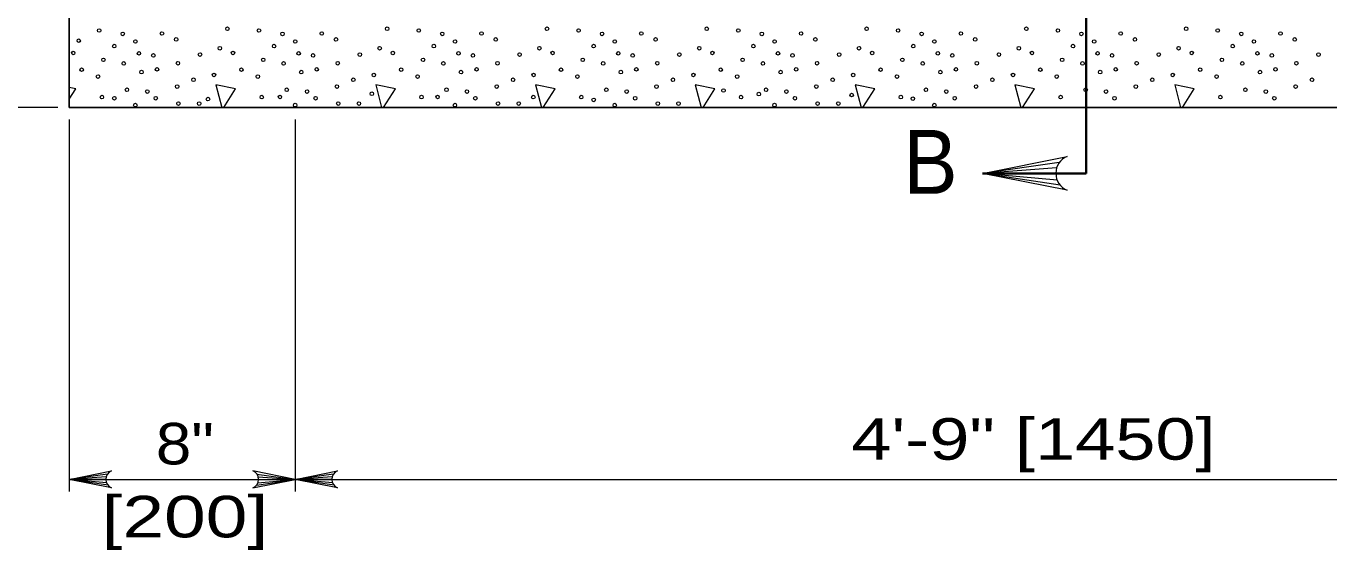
# Model space of a CAD drawing. Extents: x 1352.5 to 1386.5, y 735.9 to 779.9.
# Drawn here: x 1359.407 to 1364.306, y 769.001 to 770.968 of the extents above; entities that cross this region are included whole.
import ezdxf
from ezdxf.enums import TextEntityAlignment as Align

# ---------------------------------------------------------------- set-up
doc = ezdxf.new("R2010")
doc.units = 0
doc.header["$LTSCALE"] = 0.062
doc.layers.add('1', color=7, linetype='Continuous', lineweight=13)

msp = doc.modelspace()

# ---------------------------------------------------------------- linework, layer by layer
at = {"layer": '1', "lineweight": 35}
for p, q in [((1363.393, 771.60092), (1363.393, 770.5645)), ((1363.393, 770.5645), (1363.393, 770.41492)), ((1363.393, 770.41492), (1363.00358, 770.41492))]:
    msp.add_line(p, q, dxfattribs=at)
at = {"layer": '1'}
for p, q in [((1360.12142, 770.747), (1360.14375, 770.66242)), ((1360.19517, 770.73258), (1360.12142, 770.747)), ((1360.15067, 770.66242), (1360.19517, 770.73258)), ((1360.72225, 770.747), (1360.74442, 770.66242)), ((1360.79592, 770.73258), (1360.72225, 770.747)), ((1360.75142, 770.66242), (1360.79592, 770.73258)), ((1361.323, 770.747), (1361.34517, 770.6625)), ((1361.39667, 770.73258), (1361.323, 770.747)), ((1361.35208, 770.6625), (1361.39667, 770.73258)), ((1361.92367, 770.747), (1361.94592, 770.6625)), ((1361.9975, 770.73258), (1361.92367, 770.747)), ((1361.95283, 770.6625), (1361.9975, 770.73258)), ((1362.52442, 770.747), (1362.54667, 770.6625)), ((1362.59825, 770.73258), (1362.52442, 770.747)), ((1362.55358, 770.6625), (1362.59825, 770.73258)), ((1363.12525, 770.747), (1363.1475, 770.6625)), ((1363.726, 770.747), (1363.74825, 770.6625)), ((1363.79975, 770.73258), (1363.726, 770.747)), ((1363.75517, 770.6625), (1363.79975, 770.73258)), ((1359.52733, 770.66242), (1357.68633, 770.66242)), ((1359.56983, 770.61742), (1359.56983, 769.22067)), ((1360.41942, 770.61742), (1360.41942, 769.22067)), ((1363.29208, 770.45525), (1363.00358, 770.41492)), ((1363.28225, 770.43525), (1363.00358, 770.41492)), ((1363.27933, 770.41492), (1363.00358, 770.41492)), ((1363.28442, 770.389), (1363.00358, 770.41492)), ((1363.29542, 770.37025), (1363.00358, 770.41492)), ((1359.714, 769.28583), (1359.56983, 769.26567)), ((1359.70917, 769.27583), (1359.56983, 769.26567)), ((1359.70767, 769.26567), (1359.56983, 769.26567)), ((1359.71025, 769.25275), (1359.56983, 769.26567)), ((1359.71575, 769.24333), (1359.56983, 769.26567)), ((1360.2735, 769.24333), (1360.41942, 769.26567)), ((1360.27517, 769.28583), (1360.41942, 769.26567)), ((1360.279, 769.25275), (1360.41942, 769.26567)), ((1360.28008, 769.27583), (1360.41942, 769.26567)), ((1360.28158, 769.26567), (1360.41942, 769.26567)), ((1360.56367, 769.28583), (1360.41942, 769.26567)), ((1360.55875, 769.27583), (1360.41942, 769.26567)), ((1360.55725, 769.26567), (1360.41942, 769.26567)), ((1360.55983, 769.25275), (1360.41942, 769.26567)), ((1360.56533, 769.24333), (1360.41942, 769.26567))]:
    msp.add_line(p, q, dxfattribs=at)
at = {"layer": '1', "lineweight": 25}
msp.add_lwpolyline([(1358.38042, 774.73258), (1359.56983, 774.73258), (1359.56983, 770.66242), (1367.21625, 770.66242), (1367.21625, 774.73258), (1368.40567, 774.73258), (1369.78625, 774.73258)], dxfattribs=at)
at = {"layer": '1'}
for points in [[(1359.56983, 770.69392), (1359.59442, 770.73258), (1359.56983, 770.7375)], [(1363.15433, 770.6625), (1363.19892, 770.73258), (1363.12525, 770.747)], [(1363.32225, 770.35117), (1363.00358, 770.41492), (1363.32225, 770.47858)], [(1359.72908, 769.23383), (1359.56983, 769.26567), (1359.72908, 769.2975)], [(1359.56983, 769.26567), (1360.1195, 769.26567), (1360.41942, 769.26567), (1363.67817, 769.26567), (1366.36658, 769.26567), (1366.95142, 769.26567), (1367.21625, 769.26567)], [(1360.26008, 769.23383), (1360.41942, 769.26567), (1360.26008, 769.2975)], [(1360.57875, 769.23383), (1360.41942, 769.26567), (1360.57875, 769.2975)]]:
    msp.add_lwpolyline(points, dxfattribs=at)
for centre, radius, start, end in [((1363.34795, 770.41495), 0.06876, 112.08782, 247.91395), ((1359.74198, 769.2657), 0.03438, 112.08782, 247.91395), ((1360.24725, 769.2657), 0.03438, 292.08605, 67.91218), ((1360.59158, 769.2657), 0.03438, 112.08782, 247.91395)]:
    msp.add_arc(centre, radius, start, end, dxfattribs=at)
for centre in [(1359.68238, 770.95131), (1359.77085, 770.93843), (1359.91843, 770.94013), (1360.16449, 770.95788), (1360.28314, 770.95131), (1360.3716, 770.93843), (1360.51919, 770.94013), (1360.76525, 770.95788), (1360.8839, 770.95131), (1360.97236, 770.93843), (1361.11995, 770.94013), (1361.36601, 770.95788), (1361.48466, 770.95131), (1361.57312, 770.93843), (1361.72071, 770.94013), (1361.96677, 770.95788), (1362.08542, 770.95131), (1362.17388, 770.93843), (1362.32146, 770.94013), (1362.56752, 770.95788), (1362.68617, 770.95131), (1362.77464, 770.93843), (1362.92222, 770.94013), (1363.16828, 770.95788), (1363.28693, 770.95131), (1363.37539, 770.93843), (1363.52298, 770.94013), (1363.76904, 770.95788), (1363.88769, 770.95131), (1363.97615, 770.93843), (1364.12374, 770.94013), (1359.60548, 770.91302), (1359.73916, 770.8929), (1359.81866, 770.91007), (1359.97195, 770.91781), (1360.13611, 770.8849), (1360.33991, 770.8929), (1360.41941, 770.91007), (1360.57271, 770.91781), (1360.73686, 770.8849), (1360.94067, 770.8929), (1361.02017, 770.91007), (1361.17347, 770.91781), (1361.33762, 770.8849), (1361.54143, 770.8929), (1361.62093, 770.91007), (1361.77422, 770.91781), (1361.93838, 770.8849), (1362.14219, 770.8929), (1362.22169, 770.91007), (1362.37498, 770.91781), (1362.53914, 770.8849), (1362.74295, 770.8929), (1362.82245, 770.91007), (1362.97574, 770.91781), (1363.1399, 770.8849), (1363.3437, 770.8929), (1363.4232, 770.91007), (1363.5765, 770.91781), (1363.74065, 770.8849), (1363.94446, 770.8929), (1364.02396, 770.91007), (1364.17726, 770.91781), (1359.58481, 770.86688), (1359.69835, 770.84112), (1359.77485, 770.82766), (1359.83167, 770.86545), (1359.88599, 770.85765), (1359.97846, 770.82845), (1360.06146, 770.86089), (1360.18557, 770.86688), (1360.29911, 770.84112), (1360.37561, 770.82766), (1360.43243, 770.86545), (1360.48675, 770.85765), (1360.57922, 770.82845), (1360.66222, 770.86089), (1360.78633, 770.86688), (1360.89987, 770.84112), (1360.97637, 770.82766), (1361.03319, 770.86545), (1361.08751, 770.85765), (1361.17997, 770.82845), (1361.26298, 770.86089), (1361.38709, 770.86688), (1361.50063, 770.84112), (1361.57712, 770.82766), (1361.63395, 770.86545), (1361.68827, 770.85765), (1361.78073, 770.82845), (1361.86374, 770.86089), (1361.98784, 770.86688), (1362.10139, 770.84112), (1362.17788, 770.82766), (1362.2347, 770.86545), (1362.28902, 770.85765), (1362.38149, 770.82845), (1362.46449, 770.86089), (1362.5886, 770.86688), (1362.70214, 770.84112), (1362.77864, 770.82766), (1362.83546, 770.86545), (1362.88978, 770.85765), (1362.98225, 770.82845), (1363.06525, 770.86089), (1363.18936, 770.86688), (1363.3029, 770.84112), (1363.3794, 770.82766), (1363.43622, 770.86545), (1363.49054, 770.85765), (1363.58301, 770.82845), (1363.66601, 770.86089), (1363.79012, 770.86688), (1363.90366, 770.84112), (1363.98016, 770.82766), (1364.03698, 770.86545), (1364.0913, 770.85765), (1364.18376, 770.82845), (1364.26677, 770.86089), (1359.6164, 770.80417), (1359.67808, 770.77842), (1359.84134, 770.79501), (1359.89976, 770.80534), (1360.11418, 770.7844), (1360.21716, 770.80417), (1360.27884, 770.77842), (1360.44209, 770.79501), (1360.50052, 770.80534), (1360.71494, 770.7844), (1360.81792, 770.80417), (1360.87959, 770.77842), (1361.04285, 770.79501), (1361.10127, 770.80534), (1361.3157, 770.7844), (1361.41868, 770.80417), (1361.48035, 770.77842), (1361.64361, 770.79501), (1361.70203, 770.80534), (1361.91645, 770.7844), (1362.01943, 770.80417), (1362.08111, 770.77842), (1362.24437, 770.79501), (1362.30279, 770.80534), (1362.51721, 770.7844), (1362.62019, 770.80417), (1362.68187, 770.77842), (1362.84512, 770.79501), (1362.90355, 770.80534), (1363.11797, 770.7844), (1363.22095, 770.80417), (1363.28263, 770.77842), (1363.44588, 770.79501), (1363.50431, 770.80534), (1363.71873, 770.7844), (1363.82171, 770.80417), (1363.88338, 770.77842), (1364.04664, 770.79501), (1364.10506, 770.80534), (1359.78677, 770.72865), (1359.9755, 770.74062), (1360.03708, 770.76638), (1360.38752, 770.72865), (1360.57626, 770.74062), (1360.63784, 770.76638), (1360.98828, 770.72865), (1361.17702, 770.74062), (1361.2386, 770.76638), (1361.58904, 770.72865), (1361.77778, 770.74062), (1361.83936, 770.76638), (1362.02971, 770.72607), (1362.1898, 770.72865), (1362.37854, 770.74062), (1362.44011, 770.76638), (1362.79056, 770.72865), (1362.97929, 770.74062), (1363.04087, 770.76638), (1363.39131, 770.72865), (1363.58005, 770.74062), (1363.64163, 770.76638), (1363.99207, 770.72865), (1364.18081, 770.74062), (1364.24239, 770.76638), (1359.6927, 770.70114), (1359.73938, 770.69703), (1359.86331, 770.72202), (1359.8952, 770.69684), (1359.98036, 770.67707), (1360.05826, 770.67707), (1360.09136, 770.69359), (1360.29346, 770.70114), (1360.36178, 770.70167), (1360.46407, 770.72202), (1360.49596, 770.69684), (1360.58112, 770.67707), (1360.65902, 770.67707), (1360.70759, 770.71369), (1360.89421, 770.70114), (1360.95481, 770.70167), (1361.06483, 770.72202), (1361.09672, 770.69684), (1361.18188, 770.67707), (1361.25977, 770.67707), (1361.31453, 770.70132), (1361.49497, 770.70114), (1361.54165, 770.69084), (1361.66559, 770.72202), (1361.69748, 770.69684), (1361.78263, 770.67707), (1361.86053, 770.67707), (1362.09573, 770.70114), (1362.16251, 770.7125), (1362.26634, 770.72202), (1362.29823, 770.69684), (1362.38339, 770.67707), (1362.46129, 770.67707), (1362.5114, 770.70906), (1362.69649, 770.70114), (1362.74162, 770.69548), (1362.8671, 770.72202), (1362.89899, 770.69684), (1363.29725, 770.70114), (1363.46786, 770.72202), (1363.49975, 770.69684), (1363.898, 770.70114), (1364.06862, 770.72202), (1364.10051, 770.69684), (1359.81841, 770.67109), (1360.41916, 770.67109), (1361.01992, 770.67109), (1361.62068, 770.67109), (1362.22144, 770.67109), (1362.8222, 770.67109)]:
    msp.add_ellipse(centre, major_axis=(0, 0.0068), ratio=0.944544, dxfattribs=at)

# ---------------------------------------------------------------- texts
for s, height, width, p in [('B', 0.24, 0.95, (1362.70633, 770.338)), ('4\'-9" [1450]', 0.156, 1.3, (1362.51033, 769.3395))]:
    msp.add_text(s, height=height, dxfattribs=dict(at, width=width)).set_placement(p)
for s, width, p in [('8"', 1.15, (1360.00467, 769.32183)), ('[200]', 1.35, (1360.00467, 769.04783))]:
    msp.add_text(s, height=0.156, dxfattribs=dict(at, width=width)).set_placement(p, align=Align.CENTER)

doc.saveas('drawing.dxf')
